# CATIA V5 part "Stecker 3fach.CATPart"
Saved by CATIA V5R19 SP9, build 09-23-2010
Part number: Stecker 3fach
Revision: NONE
Definition: NONE
Nomenclature: K3
Source: Unknown
Bounding box of the stored display mesh (mm): x -1.52 to 6.6, y -1.27 to 1.27, z -21.2 to 9.41
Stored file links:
  D:\Temporäre Sachen\Lasermodul KY-008 with mounting for adjustment\Stecker 3fach.CATPart
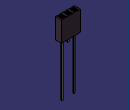
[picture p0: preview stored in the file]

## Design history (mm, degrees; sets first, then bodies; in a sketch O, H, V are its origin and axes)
AxisSystem1: origin (0, 0, 0), X (1, 0, 0), Y (0, 0, -1), Z (0, 1, 0)
Body1 "Carrera Breadboard 05_Components_K3_1" (main body)
  Solid1: solid without history
  Thickness1: Thickness -7.62, Face face of Solid1
Body2 "Carrera Breadboard 05_Components_K3_2"
  Solid2: solid without history
Body3 "Carrera Breadboard 05_Components_K3_3"
  Solid3: solid without history
Body4 "Carrera Breadboard 05_Components_K3_4"
  Solid4: solid without history
Body5 "Carrera Breadboard 05_Components_K3_8"
  Solid5: solid without history
  Thickness2: Thickness 20, Face face of Solid5
Body6 "Carrera Breadboard 05_Components_K3_9"
  Solid6: solid without history
Body7 "Carrera Breadboard 05_Components_K3_10"
  Solid7: solid without history
  Thickness3: Thickness 20, Face face of Solid7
